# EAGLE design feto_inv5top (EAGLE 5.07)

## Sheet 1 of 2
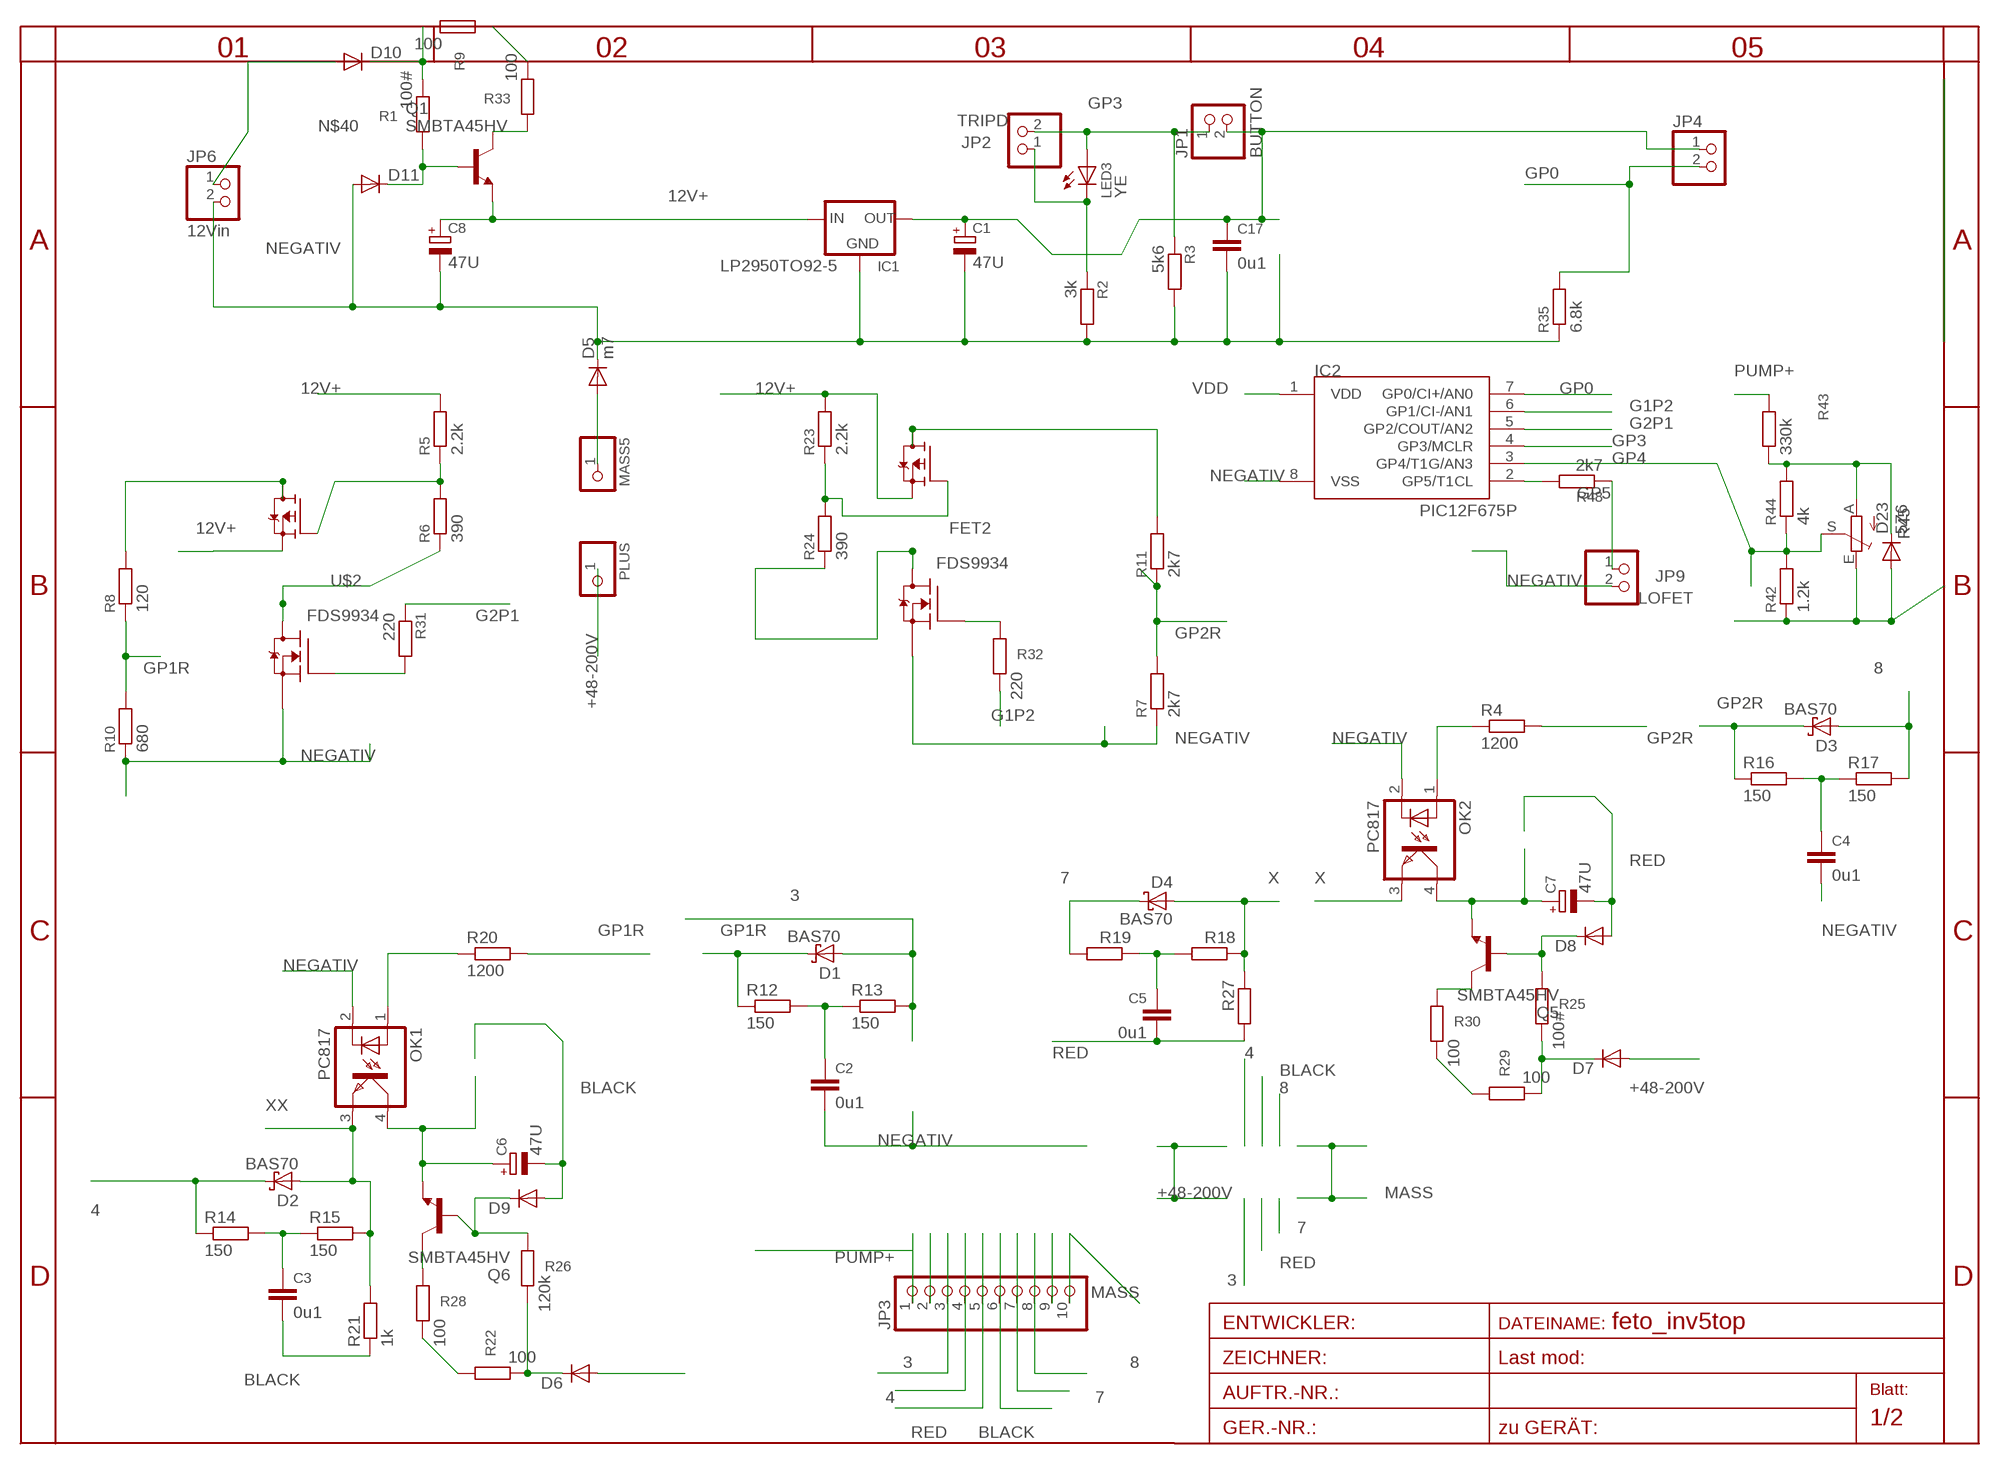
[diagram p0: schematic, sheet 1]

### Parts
C1  47U  CPOL-EUE2.5-5  [E2,5-5]
C2  0u1  C-EUC1206  [C1206]
C3  0u1  C-EUC0805  [C0805]
C4  0u1  C-EUC1206  [C1206]
C5  0u1  C-EUC0805  [C0805]
C6  47U  CPOL-EUE2.5-6  [E2,5-6]
C7  47U  CPOL-EUE2.5-6  [E2,5-6]
C8  47U  CPOL-EUE2.5-7  [E2,5-7]
C17  0u1  C-EUC1206  [C1206]
D1  BAS70  [SOT23]
D2  BAS70  [SOT23]
D3  BAS70  [SOT23]
D4  BAS70  [SOT23]
D5  m7  DIODE-SMA-DO214  [SMA-DO214AC]
D6  DIODE-SMA-DO214  [SMA-DO214AC]
D7  DIODE-SMA-DO214  [SMA-DO214AC]
D8  DIODE-MINIMELF  [MINIMELF]
D9  DIODE-MINIMELF  [MINIMELF]
D10  DIODE-SMA-DO214  [SMA-DO214AC]
D11  DIODE-MINIMELF  [MINIMELF]
D23  5Z6  DIODE-MINIMELF  [MINIMELF]
FET2  FDS9934  [SO-8]
IC1  LP2950TO92-5  [T092-5]
IC2  PIC12F675P  [DIL8]
JP1  BUTTON  PINHD-1X2STR  [1X02]
JP2  TRIPD  PINHD-1X2STR  [1X02]
JP3  PINHD-1X10  [1X10WIDE]
JP4  PINHD-1X2STR  [1X02]
JP6  12Vin  PINHD-1X2STR  [1X02]
JP9  LOFET  PINHD-1X2STR  [1X02]
LED3  YE  LEDCHIPLED_1206  [CHIPLED_1206]
MASS5  PINHD-1X11MM6  [1X1MM8]
OK1  PC817  [DIL04]
OK2  PC817  [DIL04]
PLUS  PINHD-1X11MM6  [1X1MM8]
Q1  SMBTA45HV  [SOT23HV]
Q5  SMBTA45HV  [SOT23HV]
Q6  SMBTA45HV  [SOT23HV]
R1  100#  R-EU_R1206  [R1206]
R2  3k  R-EU_R0805  [R0805]
R3  5k6  R-EU_R0805  [R0805]
R4  1200  R-EU_0204/7  [0204/7]
R5  2.2k  R-EU_R0805  [R0805]
R6  390  R-EU_R0805  [R0805]
R7  2k7  R-EU_R0805  [R0805]
R8  120  R-EU_R0805  [R0805]
R9  100  R-EU_R1206  [R1206]
R10  680  R-EU_R0805  [R0805]
R11  2k7  R-EU_R0805  [R0805]
R12  150  R-EU_R0805  [R0805]
R13  150  R-EU_R0805  [R0805]
R14  150  R-EU_R0805  [R0805]
R15  150  R-EU_R0805  [R0805]
R16  150  R-EU_R0805  [R0805]
R17  150  R-EU_R0805  [R0805]
R18  R-EU_R0805  [R0805]
R19  R-EU_R0805  [R0805]
R20  1200  R-EU_0617/17  [0617/17]
R21  1k  R-EU_R0805  [R0805]
R22  100  R-EU_R1206  [R1206]
R23  2.2k  R-EU_R0805  [R0805]
R24  390  R-EU_R0805  [R0805]
R25  100#  R-EU_R1206  [R1206]
R26  120k  R-EU_R1206  [R1206]
R27  R-EU_R0805  [R0805]
R28  100  R-EU_R1206  [R1206]
R29  100  R-EU_R1206  [R1206]
R30  100  R-EU_R1206  [R1206]
R31  220  R-EU_R1206  [R1206]
R32  220  R-EU_R1206  [R1206]
R33  100  R-EU_R1206  [R1206]
R35  6.8k  R-EU_R0805  [R0805]
R42  1.2k  R-EU_R0805  [R0805]
R43  330k  R-EU_0207/50  [0207/50]
R44  4k  R-EU_R0805  [R0805]
R45  TRIM_EU-S64W  [S64W]
R48  2k7  R-EU_R0805  [R0805]
U$2  FDS9934  [SO-8]

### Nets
3: D1.1(A) JP3.3 R13.2
4: D2.3(C) JP3.4 R14.1
7: D4.3(C) JP3.7 R19.2
8: D3.1(A) JP3.8 R17.2
12V+: C8.+ FET2.3(Q2S) IC1.3(IN) Q1.2(E) R5.2 R23.2 U$2.3(Q2S)
+48-200V: D6.A D7.A PLUS.1
BLACK: C3.2 C6.- D9.A JP3.6 R21.1
G1P2: IC2.6(GP1/CI-/AN1) R32.1
G2P1: IC2.5(GP2/COUT/AN2) R31.1
GP0: IC2.7(GP0/CI+/AN0) JP4.2 R35.2
GP1R: D1.3(C) R8.1 R10.2 R12.1 R20.2
GP2R: D3.3(C) R4.2 R7.2 R11.1 R16.1
GP3: IC2.4(GP3/MCLR) JP1.1 JP2.2 LED3.A R3.1
GP4: IC2.3(GP4/T1G/AN3) R42.2 R44.1 R45.S
GP5: JP9.1 R48.1
MASS: D5.A JP3.10 MASS5.1
N$2: FET2.2(Q1G) R32.2
N$3: C3.1 R14.2 R15.1
N$4: R5.1 R6.2 U$2.4(Q2G)
N$5: FET2.5(Q2D2) FET2.6(Q2D) R11.2
N$6: R31.2 U$2.2(Q1G)
N$7: C6.+ OK1.4(COL) Q6.2(E)
N$8: C5.1 R18.2 R19.1
N$9: FET2.7(Q1D2) FET2.8(Q1D1) R24.1
N$11: R6.1 U$2.7(Q1D2) U$2.8(Q1D1)
N$12: C2.1 R12.2 R13.1
N$13: OK2.1(A) R4.1
N$14: C7.+ OK2.4(COL) Q5.2(E)
N$15: JP2.1 LED3.C R2.1
N$16: C4.1 R16.2 R17.1
N$17: OK1.1(A) R20.1
N$20: D7.K(C) R25.1 R29.1
N$21: R8.2 U$2.5(Q2D2) U$2.6(Q2D)
N$22: FET2.4(Q2G) R23.1 R24.2
N$23: D6.K(C) R22.1 R26.1
N$24: Q6.3(C) R28.2
N$25: JP3.2
N$26: R22.2 R28.1
N$27: D9.C Q6.1(B) R26.2
N$28: R29.2 R30.1
N$31: D8.C Q5.1(B) R25.2
N$33: Q5.3(C) R30.2
N$34: JP3.9
N$35: D10.K(C) R1.1 R9.1
N$36: R9.2 R33.1
N$38: D11.C Q1.1(B) R1.2
N$39: Q1.3(C) R33.2
N$40: D10.A JP6.1
N$41: D23.C R43.1 R44.2 R45.A
N$46: IC2.2(GP5/T1CL) R48.2
NEGATIV: C1.- C2.2 C4.2 C8.- C17.2 D5.K(C) D11.A D23.A FET2.1(Q1S) IC1.2(GND) IC2.8(VSS) JP6.2 JP9.2 OK1.2(C) OK2.2(C) R2.2 R3.2 R7.1 R10.1 R35.1 R42.1 R45.E U$2.1(Q1S)
PUMP+: JP3.1 R43.2 ; also sheet 2
RED: C5.2 C7.- D8.A JP3.5 R27.2
VDD: C1.+ C17.1 IC1.1(OUT) IC2.1(VDD) JP1.2 JP4.1
X: D4.1(A) OK2.3(EMIT) R18.1 R27.1
XX: D2.1(A) OK1.3(EMIT) R15.2 R21.2

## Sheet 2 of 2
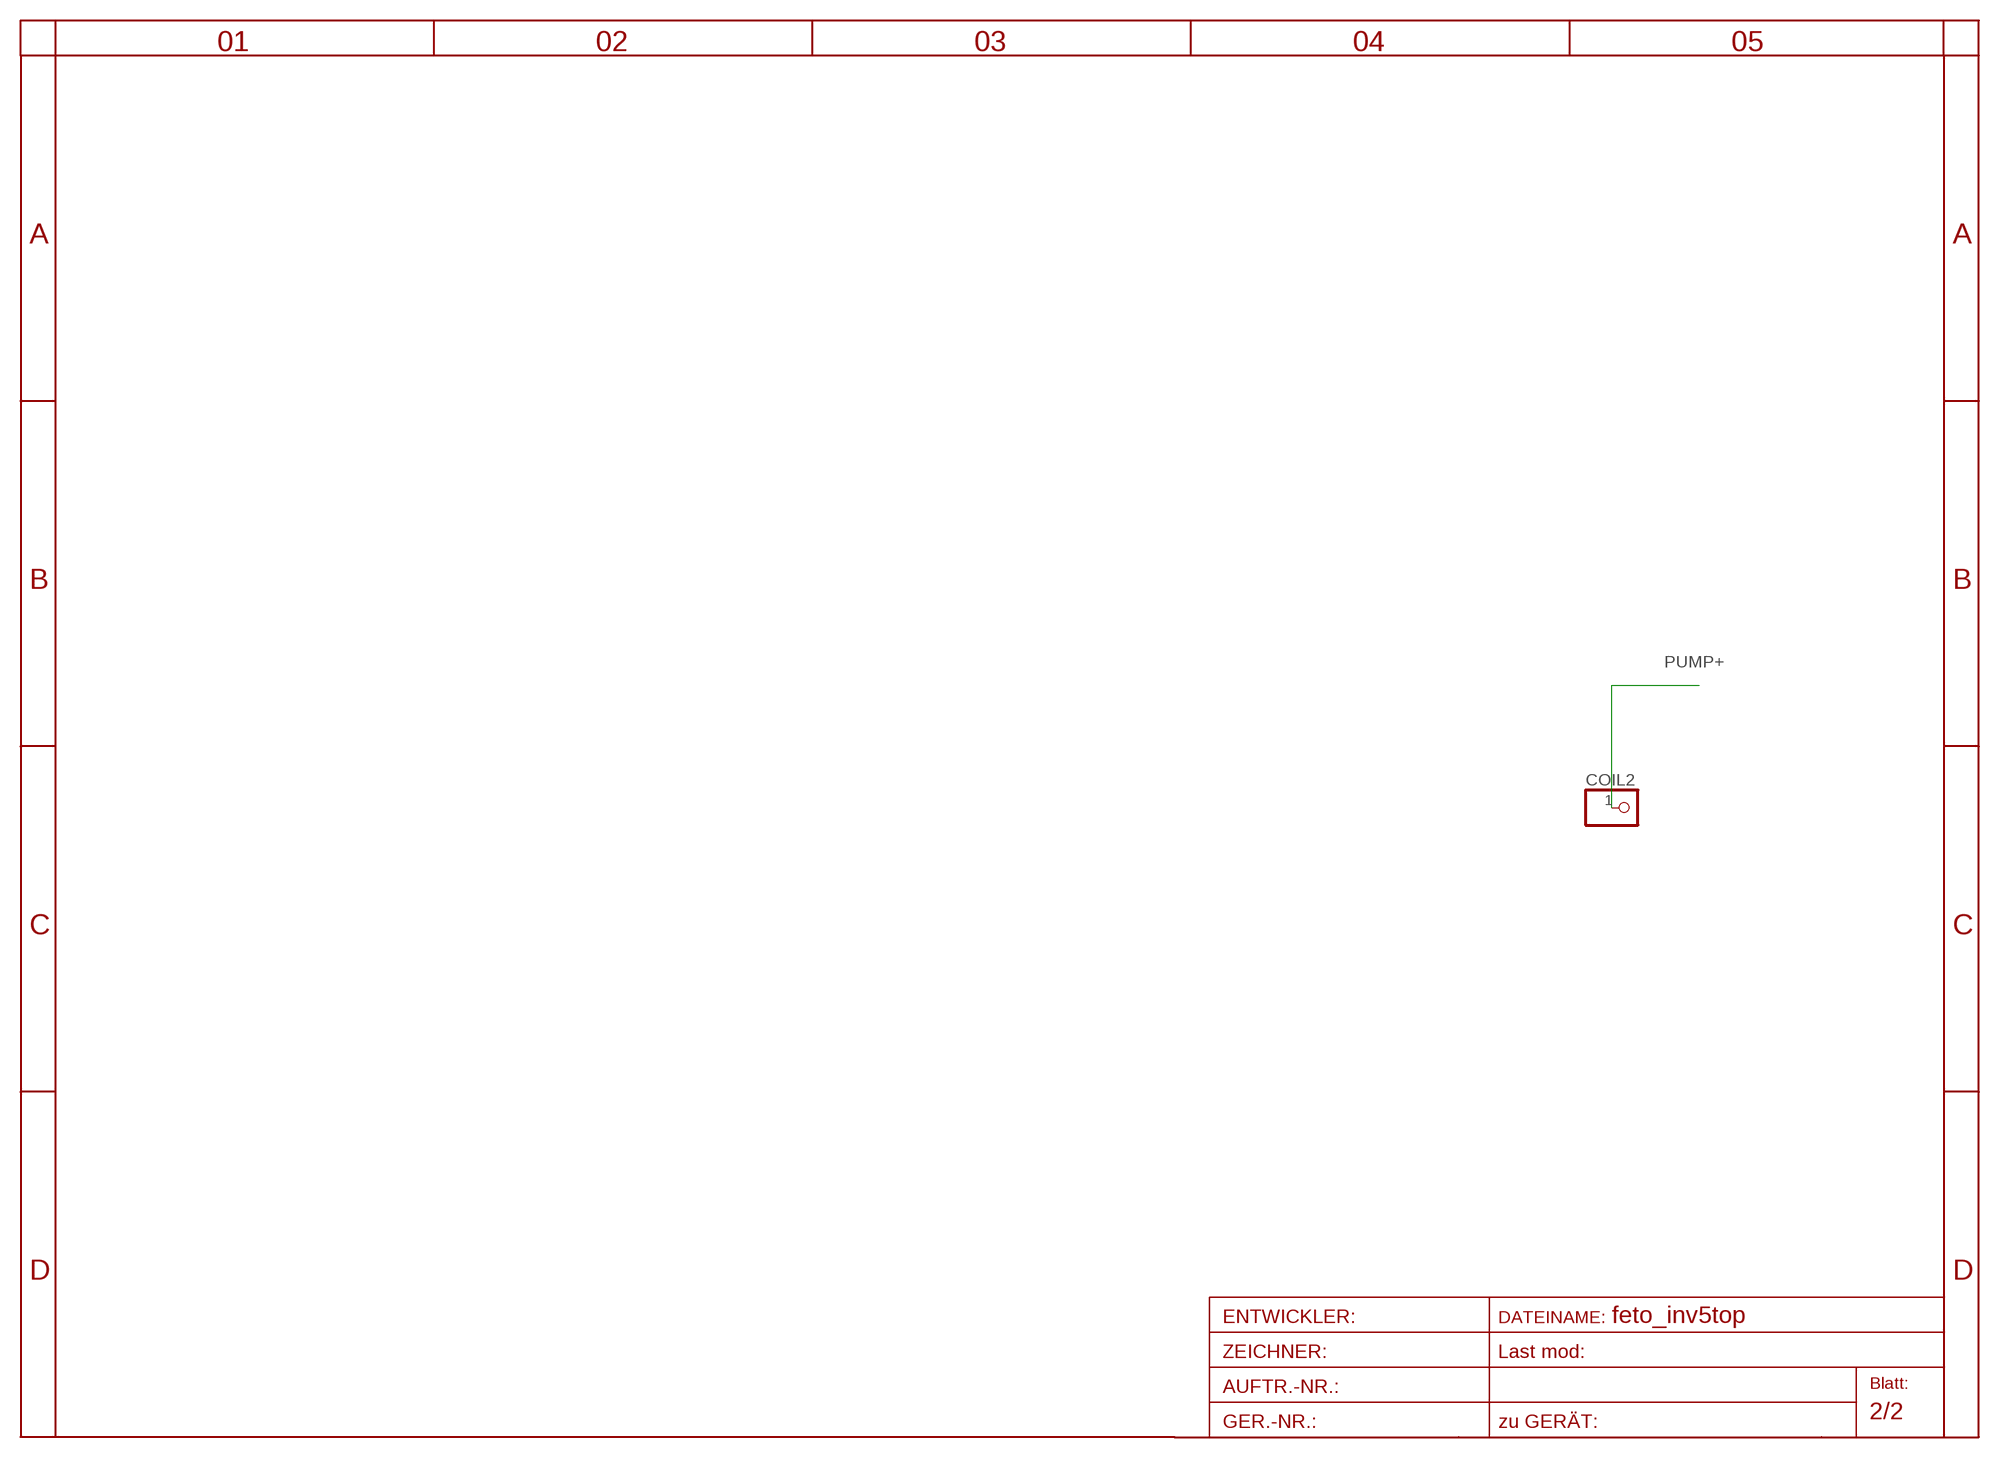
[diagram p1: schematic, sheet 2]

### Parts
COIL2  PINHD-1X14.5MM  [1X4MM5]

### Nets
PUMP+: COIL2.1 ; also sheet 1

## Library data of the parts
C1 C6-C8 = rcl-2:CPOL-EU: POLARIZED CAPACITOR, European symbol
C2-C5 C17 = rcl-2:C-EU: CAPACITOR, European symbol
COIL2 MASS5 PLUS = pinhead:PINHD-1X1: PIN HEADER
D1-D4 = diode:BAS70: Silicon Schottky Diodes
D5-D11 D23 = diode:DIODE-: DIODE
FET2 U$2 = transistor-fet:FDS9934
IC1 = v-reg:LP2950?*: Source: http://cache.national.com/ds/LP/LP2950.pdf
IC2 = microchip-3:PIC12F6*: uPC nW 1k Program Flash memory 2x Timer Comparator 10b A/D converter/ 4xIN
JP1 JP2 JP4 JP6 JP9 = pinhead:PINHD-1X2: PIN HEADER
JP3 = pinhead:PINHD-1X10: PIN HEADER
LED3 = led:LED: LED
OK1 OK2 = optocoupler:PC817: SHARP OPTO COUPLER
Q1 Q5 Q6 = transistor-npn:SMBTA45
R1-R3 R5-R11 R22-R26 R28-R33 R35 R42-R44 R48 = rcl-2:R-EU_: RESISTOR, European symbol
R4 R12-R21 R27 = rcl:R-EU_: RESISTOR, European symbol
R45 = pot:TRIM_EU-: POTENTIOMETER

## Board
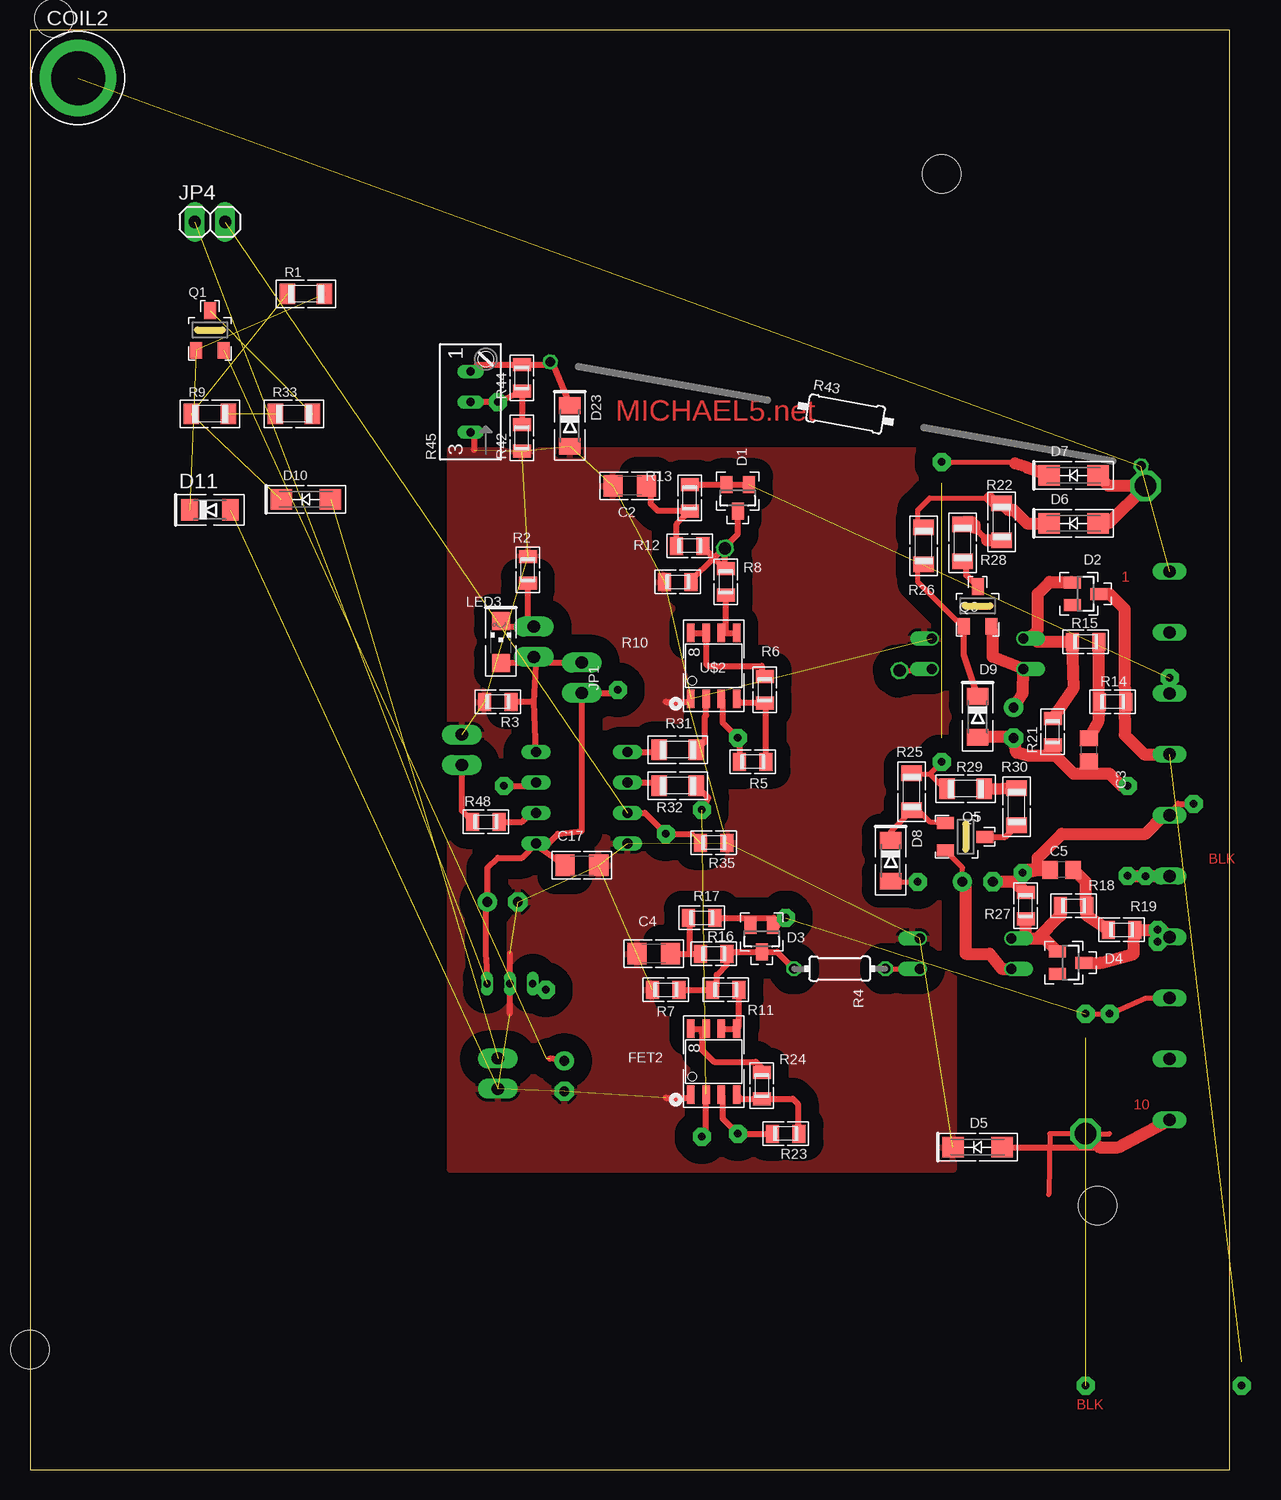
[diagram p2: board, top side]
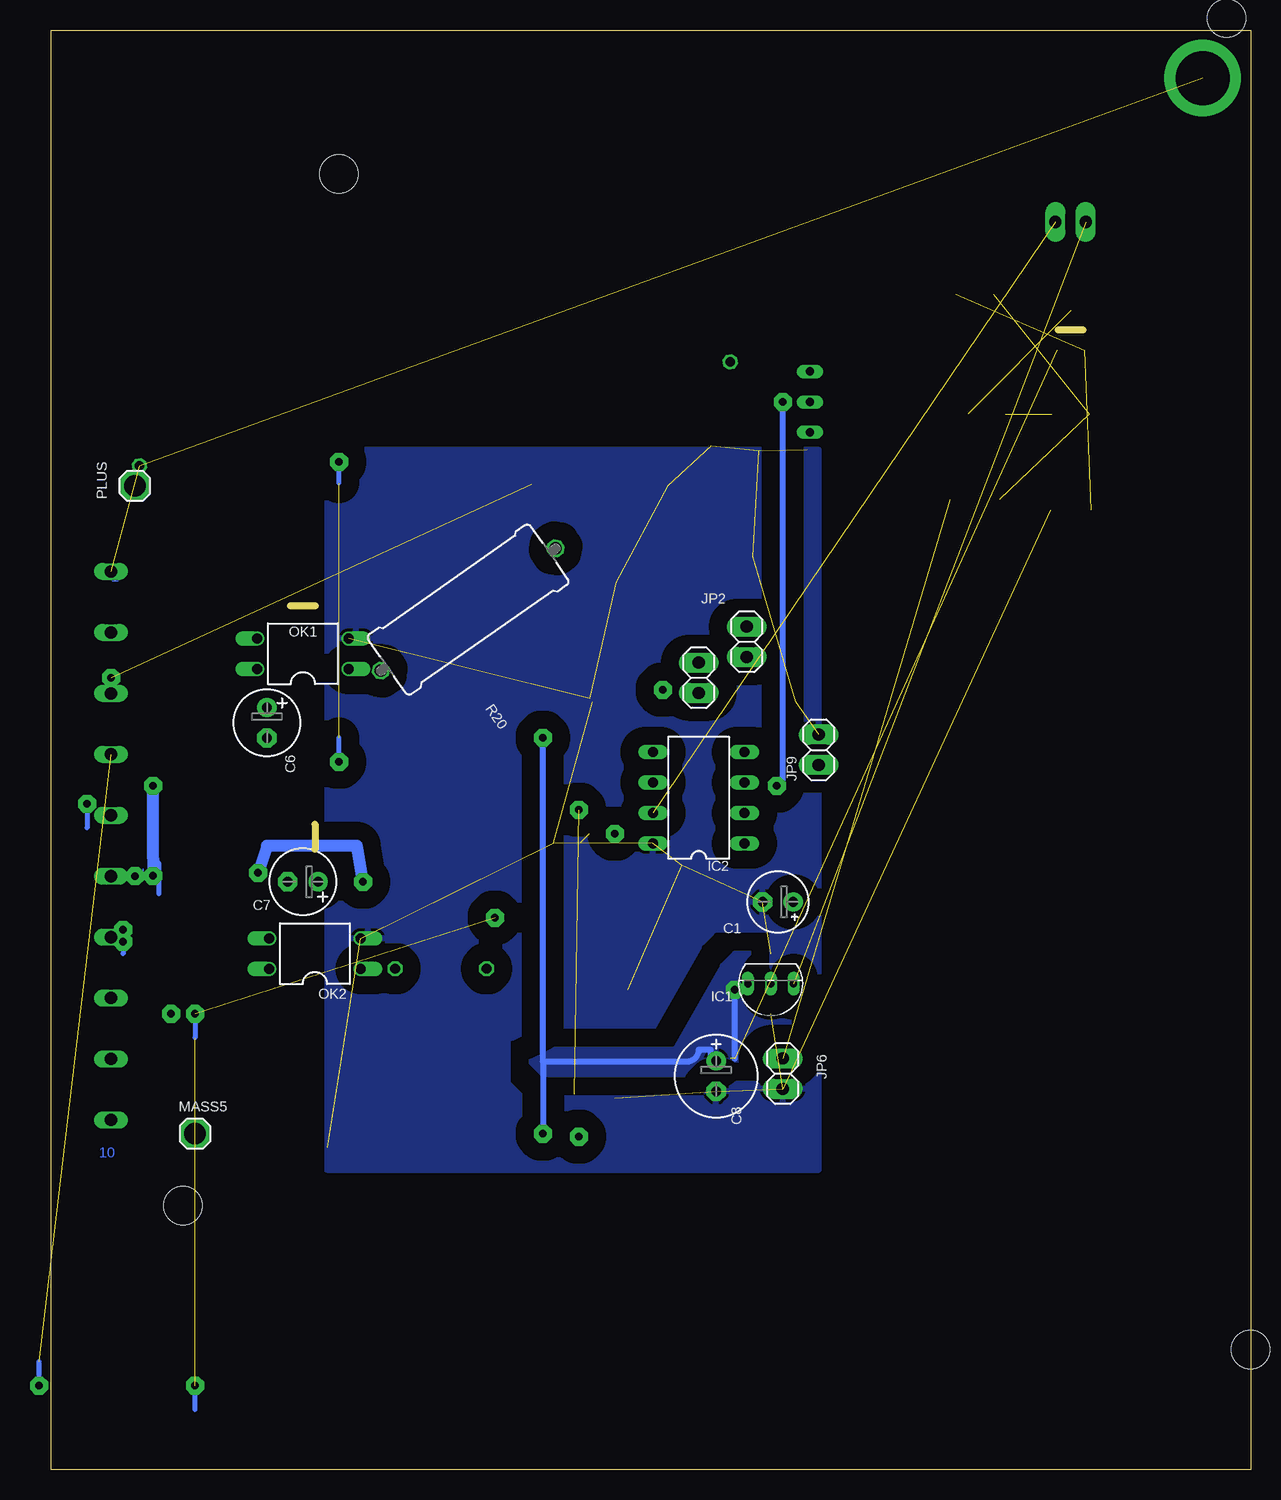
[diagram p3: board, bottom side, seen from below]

Size 100 x 120 mm. Coordinates in mm from the lower left corner, seen from the top.
Outline: 0,0 100,0 100,120 0,120 0,0
Copper layers (1*16): Top 0.035mm / dielectric 1.5mm / Bottom 0.035mm
Design rules "default *": minimum track width 12mil, minimum drill 24mil, track to track 8mil, track to pad 8mil, pad to pad 8mil, via to via 8mil, smd to smd 8mil, copper to edge 40mil, drill to drill 8mil, minimum pad ring 8mil, minimum via ring 8mil, stop-mask expansion 4mil, vias tented up to drill 0mil, thermal gap 10mil
Holes 3.2 mm at 2,121 0,10 76,108 89,22

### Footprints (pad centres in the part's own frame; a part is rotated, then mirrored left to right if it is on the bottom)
E2,5-5 = drill 0.813 pad 1.6 round: + -1.27,0 | drill 0.813 pad 1.6 octagon: - 1.27,0
C1206 = smd 1.6 x 1.8: 1 -1.4,0; 2 1.4,0
C0805 = smd 1.3 x 1.5: 1 -0.95,0; 2 0.95,0
E2,5-6 = drill 0.813 pad 1.6 round: + -1.27,0 | drill 0.813 pad 1.6 octagon: - 1.27,0
E2,5-7 = drill 0.813 pad 1.6 round: + -1.27,0 | drill 0.813 pad 1.6 octagon: - 1.27,0
1X4MM5 = drill 4.5 pad 6.35 round: 1 0,0
SOT23 = smd 1 x 1.4: 1 -0.95,-1.1; 2 0.95,-1.1; 3 0,1.1
SMA-DO214AC = smd 1.8 x 1.7: A 2.05,-0.127; K -2.05,-0.127
MINIMELF = smd 1.4 x 1.8: A 1.7,0; C -1.7,0
SO-8 = smd 1.524 x 0.61: 1 -2.743,1.905; 2 -2.743,0.635; 3 -2.743,-0.635; 4 -2.743,-1.905; 5 2.743,-1.905; 6 2.743,-0.635; 7 2.743,0.635; 8 2.743,1.905
T092-5 = drill 0.6 pad 0.813 long: 1 -1.905,0; 2 0,0; 3 1.905,0
DIL8 = drill 0.813 long: 1 -3.81,-3.81; 2 -1.27,-3.81; 3 1.27,-3.81; 4 3.81,-3.81; 5 3.81,3.81; 6 1.27,3.81; 7 -1.27,3.81; 8 -3.81,3.81
1X02 = drill 1.016 pad 1.676 long: 1 -1.27,0; 2 1.27,0
1X10WIDE = drill 1.016 long: 1 -22.86,0; 2 -17.78,0; 3 -12.7,0; 4 -7.62,0; 5 -2.54,0; 6 2.54,0; 7 7.62,0; 8 12.7,0; 9 17.78,0; 10 22.86,0
CHIPLED_1206 = smd 1.5 x 1.5: A 0,-1.75; C 0,1.75
1X1MM8 = drill 1.8 pad 2.54 octagon: 1 0,0
DIL04 = drill 0.813 offset: 1 -1.27,-3.81; 2 1.27,-3.81; 3 1.27,3.81; 4 -1.27,3.81
SOT23HV = smd 1 x 1.4: 1 -1.15,-1.7; 2 1.15,-1.7; 3 0,1.6
R1206 = smd 1.3 x 1.7: 1 -1.55,0; 2 1.55,0
R0805 = smd 1.1 x 1.5: 1 -1.1,0; 2 1.1,0
0204/7 = drill 0.813 octagon: 1 -3.81,0; 2 3.81,0
0617/17 = drill 1.016 octagon: 1 -8.89,0; 2 8.89,0
0207/50 = drill 0.813 octagon: 1 -25,0; 2 25,0
S64W = drill 0.7 long: A 2.54,1.27; E -2.54,1.27; S 0,1.27

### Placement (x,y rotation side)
C1  39.4,47.32 180 bottom
C2  50,82 180 top
C3  88.25,60 270 top
C4  52,43 180 top
C5  86,50 180 top
C6  82,62.25 270 bottom
C7  79,49 180 bottom
C8  44.55,32.8 270 bottom
C17  46.01,50.37 0 top
COIL2  4,116 0 top
D1  59,81 180 top
D2  88,73 270 top
D3  61,44.25 180 top
D4  86.75,42.25 270 top
D5  79,27 0 top
D6  87,79 0 top
D7  87,83 0 top
D8  71.75,50.75 270 top
D9  79,62.75 270 top
D10  23,81 0 top
D11  15,80 0 top
D23  45,87 270 top
FET2  57,34 90 top
IC1  40,40.5 180 bottom
IC2  46,56 90 bottom
JP1  46,66 270 bottom
JP2  42,69 270 bottom
JP3  95,52 270 bottom
JP4  15,104 0 top
JP6  39,33 270 bottom
JP9  36,60 90 bottom
LED3  39.25,69 0 top
MASS5  88,28 0 bottom
OK1  79,68 90 bottom
OK2  78,43 90 bottom
PLUS  93,82 180 bottom
Q1  15,95 0 top
Q5  78,52.75 270 top
Q6  79,72 0 top
R1  23,98 0 top
R2  41.5,75 90 top
R3  39,64 180 top
R4  67.5,41.75 180 top
R5  60.25,59 180 top
R6  61.25,65 270 top
R7  53,40 0 top
R8  58,74 270 top
R9  15,88 0 top
R10  54,74 0 top
R11  58,40 0 top
R12  55,77 180 top
R13  55,81 90 top
R14  90.25,64 180 top
R15  88,69 180 top
R16  57,43 180 top
R17  56,46 0 top
R18  87,47 0 top
R19  91,45 0 top
R20  65.22,71.69 35 bottom
R21  85.25,61.5 90 top
R22  81,79 270 top
R23  63,28 180 top
R24  61,32 270 top
R25  73.5,56.5 270 top
R26  74.5,77 270 top
R27  83,47 90 top
R28  77.75,77.25 270 top
R29  78,56.75 0 top
R30  82.25,55.25 270 top
R31  54,60 0 top
R32  54,57 0 top
R33  22,88 0 top
R35  57,52.25 180 top
R42  41,86 90 top
R43  68,88 350 top
R44  41,91 90 top
R45  38,89 90 top
R48  38,54 0 top
U$2  57,67 90 top

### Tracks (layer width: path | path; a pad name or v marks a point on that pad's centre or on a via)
3  (via drill 0.6 pad 1.5)  (1 unrouted)
  Top 0.5: R13.2 D1.1
  Top 1: JP3.3 v95,66
4  (via drill 0.6 pad 1.5)  (1 unrouted)
  Top 1: D2.3 90,73 91.25,71.75 91.25,65.5 91.35,64.4 R14.1 91.25,62.65 91.25,61.25 92.88,59.62 JP3.4
  Bottom 0.406: v101,7 101,9
7  (via drill 0.6 pad 1.5)
  Top 0.406: v94,45 v94,44
  Top 1: D4.3 89.25,42.25 92,43 92,43.9 R19.2
  Top 1.016: R19.2 v94,45 94.38,45 JP3.7
  Bottom 0.406: v94,44 94,43
8  (via drill 0.6 pad 1.5)  (2 unrouted)
  Top 0.406: JP3.8 93,39.3 v90,38 v88,38
  Top 0.5: R17.2 62,46 61.95,45.95 D3.1 62.35,45.35 v63,46
  Bottom 0.406: 88,5 v88,7 | v88,38 88,36
12V+  (via drill 0.6 pad 1.5)  (2 unrouted)
  Top 0.5: C8.+ 43.34,34.27 | R23.2 v59,28 59,28.5 58.5,28.5 57.75,29.25 57.75,31.14 FET2.3 | R5.2 59.15,60.85 v59,61 57.75,62.25 57.75,64.14 U$2.3 | IC1.3 42.41,40 v43,40
  Bottom 0.5: 59,34 v59,28 | 59,34 v59,61 | 43,34.27 v43,40 | C8.+ arc90 45,34.52 45,35 46,35 arc90 47,34 59,34
  pour Bottom (isolate 2, rank 2): 41,43 43,43 44,42 48,35 58,35 60,34 59,33 38,33 37,34
+48-200V
  Top 0.406: PLUS.1 93,83.28
  Top 1: D7.A 89.92,82 PLUS.1 89.87,78.87 D6.A
BLACK  (via drill 0.6 pad 1.5)
  Top 0.406: 85,59.5 R21.1
  Top 1: JP3.6 v93,49.46 92.29,49.46 v91.5,49.5 | v91.5,57 91,57 90,58 88,58 | C6.- 82.23,59.77 83.25,59.5 85,59.5 85.5,59.5 87,58 88,58 | C3.2 88.25,58.25 88,58
  Top 1.016: D9.A 81.68,61.05 C6.-
  Bottom 0.406: 91.5,51 91,50.5 91,48
  Bottom 1: v91.5,57 91.5,51 v91.5,49.5
G1P2
  Top 0.5: IC2.6 52.18,57.27 R32.1
G2P1
  Top 0.5: IC2.5 52.26,59.81 R31.1
GP0  (via drill 0.6 pad 1.5)  (2 unrouted)
  Top 0.5: IC2.7 51.27,54.73 v53,53 55.15,53
GP1R
  Top 0.5: R10.2 55.1,74.1 57,76 | 57,76 59,78 D1.3 | R12.1 56.1,76.9 57,76 | 57,76 57.9,75.1 R8.1 57.93,75.17 R20.2
GP2R
  Top 0.5: R7.2 R11.1 57.25,40.35 57.25,41.25 58.1,42.1 R16.1 58.25,43.15 D3.3 62.29,43.15 R4.2
GP3
  Top 0.5: IC2.4 42,64 | 42,64 42.19,67 | 42.19,67 42.19,67.54 JP2.2 42.46,67.27 JP1.1 | 42,64 R3.1 | LED3.A 41.94,67.25 42.19,67
GP4  (via drill 0.6 pad 1.5)
  Top 0.5: IC2.3 41.92,57 v39.5,57 | R42.2 R44.1 v39,89 R45.S
  Bottom 0.5: v39.5,57 39,57.5 v39,89
GP5
  Top 0.5: JP9.1 36,54.9 R48.1
MASS
  Top 0.406: 84.92,22.92 85,28 MASS5.1 90,28
  Top 0.5: D5.A 89.13,26.87
  Top 1: MASS5.1 89.13,26.87 90.73,26.87 JP3.10
N$2  (via drill 0.6 pad 1.5)  (1 unrouted)
  Top 0.5: R32.2 56.55,56 v56,55 | v56,27.75 56.37,27.64 FET2.2
N$3
  Top 1: R15.1 89.1,62.8 R14.2 89.1,62.45 C3.1
N$4
  Top 0.5: U$2.4 59.26,63.9 R6.2 61.35,63.8 R5.1
N$5
  Top 0.5: FET2.6 FET2.5 59.1,36.94 R11.2
N$6
  Top 0.5: R31.2 56.25,60.7 56.25,62.75 56.37,62.87 U$2.2
N$7
  Top 0.5: Q6.2 80.15,69.95 80.25,69.85
  Top 1: 80.25,69.85 80.25,68.5 80.27,67.73 OK1.4 82.77,64.69 C6.+
N$8
  Top 1: R19.1 88.1,46.2 R18.2 88,47.1 88,49 87,50 C5.1
N$9
  Top 0.5: FET2.8 FET2.7 56,36.38 56,35 57,34 60.5,34 61,33.5 R24.1
N$11
  Top 0.5: R6.1 61,66.35 61,67 56.5,67 56.37,67.14 U$2.7 U$2.8
N$12
  Top 0.5: R12.2 53.9,78.8 R13.1 52.35,79.9 51.75,80.5 51.75,81.65 C2.1
N$13
  Top 0.406: R4.1 74.17,41.75 OK2.1
N$14
  Top 0.406: Q5.2 77.73,50.17 C7.+ 78,48.73
  Top 1: OK2.4 81.02,41.73 80,43 78,43 78,48.73
N$15
  Top 0.5: LED3.C 39.73,70.27 JP2.1 41.5,70.77 R2.1
N$16
  Top 0.5: C4.1 55,43 | 55,43 R16.2 | R17.1 55,45.9 55,43
N$17
  Top 0.406: R20.1 75.05,66.59 OK1.1
N$20  (via drill 0.6 pad 1.5)  (1 unrouted)
  Top 0.406: R29.1 76.25,56.75 75,58 | 75,58 73.55,58 R25.1 | 75,58 v76,59 | v76,84 82.68,84 83.18,83.5
  Top 0.5: 82.13,83.87 82,84
  Top 1: 82.13,83.87 83.18,83.5 D7.K
  Bottom 0.406: v76,59 76,61 | 76,82.25 v76,84
N$21
  Top 0.5: U$2.5 U$2.6 57.74,69.74 58,70 R8.2
N$22
  Top 0.5: FET2.4 59.26,30.9 R24.2 63.6,30.9 64,30.5 64,28.1 R23.1
N$23
  Top 0.406: 80,81 75,81 74,80 74,79.05 R26.1
  Top 1: 80,81 80.45,80.55 R22.1 81.55,80 82,80 83.13,78.87 D6.K
N$24
  Top 0.5: 78.05,75.7 78.05,74.55 Q6.3
  Top 1: 78.05,75.7 R28.2
N$26
  Top 0.5: 79.8,77.45 78.75,78.5 | 78.75,78.75 78.5,79
  Top 1: R22.2 79.8,77.45 | 78.75,78.5 78.75,78.75 | 78.5,79 77.95,79 R28.1
N$27
  Top 0.406: 77.7,70.3 74,74 74,74.95 R26.2
  Top 0.5: D9.C 77.85,67.95 Q6.1 77.7,70.3
N$28
  Top 1: R29.2 79.7,56.75 R30.1
N$31
  Top 0.406: D8.C 71.75,53.2 R25.2 74.05,54.95 75,54 76.2,54 Q5.1
N$33
  Top 0.5: Q5.3 81.3,52.75 R30.2
N$35  (2 unrouted)
N$36  (1 unrouted)
N$38  (2 unrouted)
N$39  (1 unrouted)
N$40  (1 unrouted)
N$41
  Top 0.5: 43.6,92.1 D23.C | 43.6,92.1 R44.2 37.29,92.1 R45.A | 43.6,92.1 43.6,92.12 R43.1
N$46
  Top 0.5: R48.2 41,54 42,55 42,54.92 IC2.2
NEGATIV  (22 unrouted)
  Top 0.5: R45.E 37,86.19 37,85 | U$2.1 54.84,64 53,64 | FET2.1 54.84,31 53,31 | 40,43 IC1.2 40,38
  pour Top (isolate 1.5, rank 4): 35,85 77,85 77,25 35,25
  pour Bottom (isolate 1.5, rank 3): 36,85 77,85 77,25 36,25
PUMP+  (2 unrouted)
RED  (via drill 0.6 pad 1.5)
  Top 0.406: v74,49 71.8,49 D8.A
  Top 0.5: v97,55.5 95.71,55.5 JP3.5
  Top 1: 82.1,49 C7.- | 82.1,49 R27.2 | 84,50 83.1,50 82.1,49 | 84,50 C5.2 | JP3.5 94.54,54.54 93,53 86,53 84,51 84,50 | v82.75,49.75 84,50
  Bottom 0.406: v97,55.5 97,53.5
  Bottom 1: v74,49 74.5,52 82,52 v82.75,49.75
VDD  (via drill 0.6 pad 1.5)  (1 unrouted)
  Top 0.5: JP1.2 46,64.98 | JP1.2 46,53.25 44,53 43,52 42.38,52 IC2.1 | C17.1 42.61,51.77 IC2.1 | IC2.1 41,51 39,51 38.13,50.13 C1.+ 38,47.19 38,43 38.09,41.91 IC1.1 | JP1.2 48.73,64.73 v49,65
X
  Top 1: OK2.3 83,44.27 | 83,44.27 84,44.27 | 84,44.27 84.58,44.27 D4.1 | R18.1 85.9,46.17 84,44.27 | 83,44.27 R27.1
XX
  Top 1: OK1.3 83.27,69.27 83.5,69.5 | 83.5,69.5 84,70 84,73 85,74 86.85,74 D2.1 | 83.5,69.5 84,69 R15.2 87,65.15 R21.2

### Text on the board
Top: MICHAEL5.net | 1 | BLK | 10 | BLK
Bottom: 1 | BLK | 10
